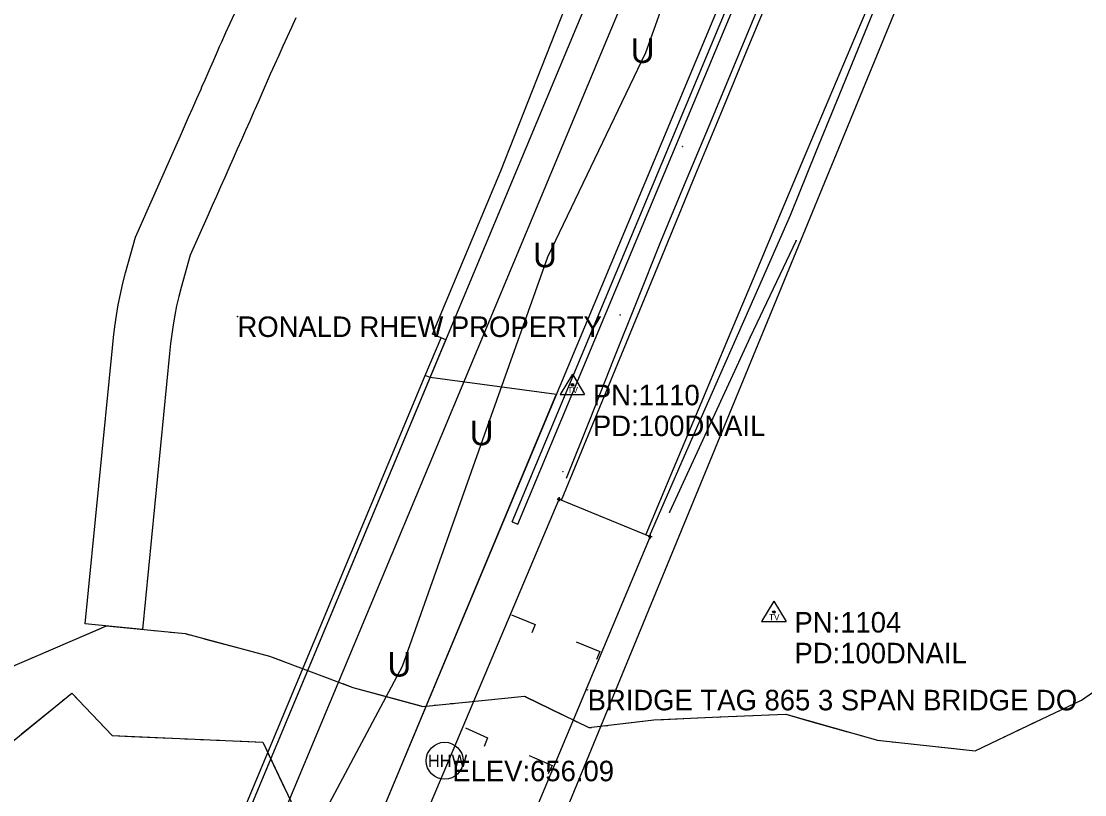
# Model space of a CAD drawing. Extents: x 1282810 to 1284464, y 402460 to 405899.
# Drawn here: x 1283291.6 to 1283550.7, y 403871.1 to 404059.6 of the extents above; entities that cross this region are included whole.
import ezdxf

# ---------------------------------------------------------------- set-up
doc = ezdxf.new("R2010")
doc.units = 0
for name, color, linetype in [('Default', 7, 'Continuous'), ('MOT_Bridge_Stage 2', 7, 'Continuous'), ('MOT_Proposed Road_Stage 2', 7, 'Continuous'), ('MOT_Shld_Stage 2', 7, 'Continuous'), ('MOT_Stage 1_Conc Ditch Paving', 7, 'Continuous'), ('MOT_Stage 2_Retaining Wall', 7, 'Continuous'), ('S_BASELINE', 7, 'Continuous'), ('S_BRIDGE', 7, 'Continuous'), ('S_EDGE_CONCRETE', 7, 'Continuous'), ('S_EDGE_PAVEMENT', 7, 'Continuous'), ('S_GUARDRAIL', 7, 'Continuous'), ('S_HIST_HIGH_WATER', 7, 'Continuous'), ('S_HIST_HIGH_WATER_ANNOT', 7, 'Continuous'), ('S_MSC_PT_SYM', 7, 'Continuous'), ('S_RDW_PT_SYM', 7, 'Continuous'), ('S_SECONDARY_CTL', 7, 'Continuous'), ('S_SECONDARY_CTL_ANNOT', 7, 'Continuous'), ('S_SHOULDER', 7, 'Continuous'), ('S_STR_PT_SYM', 7, 'Continuous'), ('S_STREAM', 7, 'Continuous'), ('S_SURVEY_TEXT_ANNOT', 7, 'Continuous'), ('S_UNDERGROUND_CABLE', 7, 'Continuous')]:
    doc.layers.add(name, color=color, linetype=linetype)

msp = doc.modelspace()

# ---------------------------------------------------------------- linework, layer by layer
at = {"layer": 'MOT_Bridge_Stage 2'}
for p, q in [((1283390.08, 403973.25), (1283393.94, 403982.47)), ((1283395.09, 403981.99), (1283393.94, 403982.47)), ((1283391.24, 403972.77), (1283395.09, 403981.99)), ((1283326.31, 403820.53), (1283390.08, 403973.25)), ((1283327.46, 403820.05), (1283391.24, 403972.77)), ((1283391.24, 403972.77), (1283390.08, 403973.25)), ((1283391.24, 403972.77), (1283390.08, 403973.25)), ((1283422.02, 403968.62), (1283391.24, 403972.77)), ((1283358.34, 403816.13), (1283421.92, 403968.39))]:
    msp.add_line(p, q, dxfattribs=at)
at = {"layer": 'MOT_Proposed Road_Stage 2'}
for p, q in [((1283334.68, 403816.57), (1283508.7, 404233.27)), ((1283354.98, 403808.09), (1283529, 404224.79))]:
    msp.add_line(p, q, dxfattribs=at)
at = {"layer": 'MOT_Shld_Stage 2'}
for p, q in [((1283327.3, 403819.65), (1283501.32, 404236.35)), ((1283327.3, 403819.65), (1283501.32, 404236.35)), ((1283327.3, 403819.65), (1283501.32, 404236.35)), ((1283327.3, 403819.65), (1283501.32, 404236.35)), ((1283327.3, 403819.65), (1283501.32, 404236.35)), ((1283327.3, 403819.65), (1283501.32, 404236.35)), ((1283408.48, 404023.13), (1283472.69, 404185.96)), ((1283391.86, 403983.34), (1283408.48, 404023.13)), ((1283393.94, 403982.47), (1283391.86, 403983.34))]:
    msp.add_line(p, q, dxfattribs=at)
at = {"layer": 'MOT_Stage 1_Conc Ditch Paving'}
msp.add_line((1283321.17, 403911.4), (1283307.24, 403912.77), dxfattribs=at)
for points in [[(1283319.47, 404007.02), (1283329.39, 404029.36), (1283330.4, 404031.65), (1283331.41, 404033.93), (1283332.42, 404036.22), (1283333.43, 404038.5), (1283334.43, 404040.79), (1283335.44, 404043.08), (1283335.67, 404043.6), (1283336.44, 404045.37), (1283337.44, 404047.65), (1283338.44, 404049.94), (1283339.44, 404052.23), (1283339.98, 404053.47), (1283340.48, 404054.56), (1283341.51, 404056.84), (1283342.55, 404059.11), (1283343.58, 404061.39)], [(1283358.5, 404060.42), (1283357.46, 404058.11), (1283356.42, 404055.83), (1283355.39, 404053.55), (1283354.36, 404051.27), (1283353.32, 404049), (1283352.84, 404047.94), (1283352.32, 404046.75), (1283351.32, 404044.46), (1283350.32, 404042.17), (1283349.32, 404039.88), (1283348.54, 404038.11), (1283348.31, 404037.58), (1283347.31, 404035.29), (1283346.3, 404033), (1283345.29, 404030.71), (1283344.28, 404028.42), (1283343.27, 404026.13), (1283342.25, 404023.85), (1283341.24, 404021.56), (1283340.22, 404019.27), (1283339.2, 404016.99), (1283338.18, 404014.7), (1283337.16, 404012.42), (1283332.77, 404002.62)], [(1283307.24, 403912.77), (1283313.85, 403980.02), (1283314.11, 403982.58), (1283314.44, 403985.23), (1283314.83, 403987.88), (1283315.28, 403990.51), (1283315.81, 403993.14), (1283316.4, 403995.75), (1283317.05, 403998.34), (1283319.47, 404007.02)], [(1283332.77, 404002.62), (1283330.58, 403994.75), (1283330.01, 403992.5), (1283329.5, 403990.23), (1283329.05, 403987.95), (1283328.65, 403985.66), (1283328.31, 403983.36), (1283328.03, 403981.05), (1283327.79, 403978.64), (1283321.17, 403911.4)]]:
    msp.add_lwpolyline(points, dxfattribs=at)
at = {"layer": 'MOT_Stage 2_Retaining Wall'}
for p, q in [((1283411.24, 403937.63), (1283530.85, 404224.02)), ((1283412.63, 403937.05), (1283532.23, 404223.44)), ((1283411.24, 403937.63), (1283412.63, 403937.05))]:
    msp.add_line(p, q, dxfattribs=at)
at = {"layer": 'S_BASELINE'}
msp.add_line((1283396.79, 403800.11), (1283700.58, 404538.68), dxfattribs=at)
at = {"layer": 'S_BRIDGE'}
for p, q in [((1283386.52, 403857.44), (1283422.73, 403943.16)), ((1283422.73, 403943.16), (1283444.84, 403934.02)), ((1283444.84, 403934.02), (1283408.77, 403848.06))]:
    msp.add_line(p, q, dxfattribs=at)
at = {"layer": 'S_EDGE_CONCRETE'}
for points in [[(1283411.07, 403914.97), (1283416.87, 403912.6), (1283416.03, 403910.58)], [(1283426.84, 403908.35), (1283432.62, 403906.02), (1283431.79, 403904.09)], [(1283399.84, 403887.41), (1283405.22, 403884.99), (1283404.41, 403882.88)], [(1283415.38, 403880.64), (1283420.95, 403878.2), (1283420.05, 403876.23)]]:
    msp.add_lwpolyline(points, dxfattribs=at)
at = {"layer": 'S_EDGE_PAVEMENT'}
for points in [[(1283501.97, 404072.63), (1283495.51, 404057.64), (1283489.28, 404042.83), (1283483.05, 404028.02), (1283476.82, 404013.2), (1283470.59, 403998.39), (1283463.89, 403982.42), (1283457.19, 403966.45), (1283450.49, 403950.48), (1283443.8, 403934.51)], [(1283475.3, 404069.12), (1283468.85, 404053.54), (1283462.4, 404037.96), (1283455.95, 404022.37), (1283447.76, 404002.49), (1283439.57, 403982.61), (1283431.38, 403962.73), (1283423.18, 403942.85)]]:
    msp.add_lwpolyline(points, dxfattribs=at)
at = {"layer": 'S_GUARDRAIL'}
for p, q in [((1283480.45, 404006.2), (1283469.2, 403982.66)), ((1283469.2, 403982.66), (1283449.54, 403939.94))]:
    msp.add_line(p, q, dxfattribs=at)
at = {"layer": 'S_HIST_HIGH_WATER'}
msp.add_circle((1283394.8, 403879.4), 4.5, dxfattribs=at)
at = {"layer": 'S_MSC_PT_SYM'}
for points in [[(1283344.32, 403987.67), (1283344.32, 403987.72), (1283344.32, 403987.67), (1283344.27, 403987.67), (1283344.32, 403987.67), (1283344.32, 403987.62), (1283344.32, 403987.67), (1283344.37, 403987.67)], [(1283429.63, 403896.68), (1283429.63, 403896.73), (1283429.63, 403896.68), (1283429.58, 403896.68), (1283429.63, 403896.68), (1283429.63, 403896.63), (1283429.63, 403896.68), (1283429.68, 403896.68)]]:
    msp.add_lwpolyline(points, dxfattribs=at)
at = {"layer": 'S_RDW_PT_SYM'}
for points in [[(1283452.72, 404029.12), (1283452.72, 404029.17), (1283452.72, 404029.12), (1283452.67, 404029.12), (1283452.72, 404029.12), (1283452.72, 404029.07), (1283452.72, 404029.12), (1283452.77, 404029.12)], [(1283480.45, 404006.2), (1283480.45, 404006.25), (1283480.45, 404006.2), (1283480.4, 404006.2), (1283480.45, 404006.2), (1283480.45, 404006.15), (1283480.45, 404006.2), (1283480.5, 404006.2)], [(1283437.56, 403988.04), (1283437.56, 403988.09), (1283437.56, 403988.04), (1283437.51, 403988.04), (1283437.56, 403988.04), (1283437.56, 403987.99), (1283437.56, 403988.04), (1283437.61, 403988.04)], [(1283469.2, 403982.66), (1283469.2, 403982.71), (1283469.2, 403982.66), (1283469.15, 403982.66), (1283469.2, 403982.66), (1283469.2, 403982.61), (1283469.2, 403982.66), (1283469.25, 403982.66)], [(1283423.6, 403949.86), (1283423.6, 403949.91), (1283423.6, 403949.86), (1283423.55, 403949.86), (1283423.6, 403949.86), (1283423.6, 403949.81), (1283423.6, 403949.86), (1283423.65, 403949.86)], [(1283449.54, 403939.94), (1283449.54, 403939.99), (1283449.54, 403939.94), (1283449.49, 403939.94), (1283449.54, 403939.94), (1283449.54, 403939.89), (1283449.54, 403939.94), (1283449.59, 403939.94)]]:
    msp.add_lwpolyline(points, dxfattribs=at)
at = {"layer": 'S_SECONDARY_CTL'}
for p, q in [((1283425.92, 403973.63), (1283422.91, 403968.67)), ((1283425.92, 403973.63), (1283428.87, 403968.67)), ((1283422.91, 403968.67), (1283428.87, 403968.67)), ((1283475.02, 403918.25), (1283472.01, 403913.3)), ((1283475.02, 403918.25), (1283477.97, 403913.3)), ((1283472.01, 403913.3), (1283477.97, 403913.3))]:
    msp.add_line(p, q, dxfattribs=at)
for centre, radius in [((1283425.92, 403971.02), 0.311), ((1283425.92, 403971.02), 0.183), ((1283425.92, 403971.02), 0.103), ((1283475.02, 403915.64), 0.311), ((1283475.02, 403915.64), 0.183), ((1283475.02, 403915.64), 0.103)]:
    msp.add_circle(centre, radius, dxfattribs=at)
at = {"layer": 'S_SHOULDER'}
for points in [[(1283444.67, 403934.14), (1283453.25, 403953.69), (1283461.84, 403973.25), (1283470.43, 403992.81), (1283479.02, 404012.36), (1283485.34, 404027.85), (1283491.67, 404043.34), (1283497.99, 404058.83), (1283504.32, 404074.32), (1283510.99, 404088.84), (1283517.66, 404103.36), (1283524.33, 404117.88), (1283530.99, 404132.4), (1283537.64, 404146.88), (1283544.28, 404161.36), (1283550.92, 404175.84), (1283557.57, 404190.32), (1283563.12, 404202.23), (1283568.68, 404214.14), (1283574.24, 404226.06), (1283579.8, 404237.97), (1283579.85, 404238.09)], [(1283424.49, 403948.25), (1283430.23, 403962.66), (1283435.97, 403977.08), (1283441.72, 403991.49), (1283447.46, 404005.9), (1283453.25, 404019.79), (1283459.04, 404033.69), (1283464.83, 404047.59), (1283470.62, 404061.49), (1283476.77, 404076.07), (1283482.91, 404090.66), (1283489.05, 404105.25), (1283495.2, 404119.83), (1283500.76, 404133.93), (1283506.32, 404148.02), (1283514.46, 404173.11)]]:
    msp.add_lwpolyline(points, dxfattribs=at)
at = {"layer": 'S_STR_PT_SYM'}
for points in [[(1283422.73, 403943.16), (1283422.73, 403943.66), (1283422.73, 403943.16), (1283422.23, 403943.16), (1283422.73, 403943.16), (1283422.73, 403942.66), (1283422.73, 403943.16), (1283423.23, 403943.16)], [(1283444.84, 403934.02), (1283444.84, 403934.52), (1283444.84, 403934.02), (1283444.34, 403934.02), (1283444.84, 403934.02), (1283444.84, 403933.52), (1283444.84, 403934.02), (1283445.34, 403934.02)]]:
    msp.add_lwpolyline(points, dxfattribs=at)
at = {"layer": 'S_STREAM'}
for points in [[(1283277.03, 403897.09), (1283294.74, 403904.68), (1283312.44, 403912.26), (1283331.55, 403910.38), (1283352.1, 403904.92), (1283372.45, 403897.28), (1283389.44, 403892.64), (1283414.28, 403895.1), (1283429.96, 403887.46), (1283445.73, 403889.38), (1283461.81, 403890.06), (1283477.9, 403890.73), (1283500.23, 403884.39), (1283524.02, 403881.83), (1283536.98, 403887.99), (1283549.94, 403894.16), (1283563.09, 403903.37)], [(1283301.87, 403907.73), (1283310.94, 403911.62)], [(1283310.95, 403911.62), (1283312.44, 403912.26), (1283320.66, 403911.45)], [(1283323.97, 403911.13), (1283324.69, 403911.06)], [(1283327.9, 403910.74), (1283328.62, 403910.67)], [(1283331.83, 403910.31), (1283332.52, 403910.12)], [(1283336.22, 403909.14), (1283345.76, 403906.6)], [(1283294.06, 403904.39), (1283294.72, 403904.67)], [(1283297.69, 403905.94), (1283298.35, 403906.22)], [(1283345.77, 403906.6), (1283352.1, 403904.92), (1283355.21, 403903.75)], [(1283365.73, 403899.8), (1283366.4, 403899.55)], [(1283369.99, 403898.2), (1283372.45, 403897.28), (1283379.44, 403895.37)], [(1283155.14, 403780.67), (1283168.76, 403789.1), (1283182.38, 403797.52), (1283197.41, 403805.48), (1283208.78, 403811.07), (1283220.16, 403816.66), (1283233.26, 403832.25), (1283245.23, 403846.1), (1283257.2, 403859.95), (1283270.89, 403870.02), (1283284.59, 403880.1), (1283303.96, 403895.89), (1283313.81, 403885.53), (1283332.16, 403884.74), (1283350.5, 403883.96), (1283361.12, 403861.52), (1283371.83, 403855.95), (1283372.66, 403855.71)], [(1283301.7, 403894.05), (1283302.24, 403894.49)], [(1283304.62, 403895.19), (1283305.1, 403894.69)], [(1283379.44, 403895.37), (1283388.97, 403892.77)], [(1283404.66, 403894.15), (1283414.28, 403895.1), (1283414.46, 403895.02)], [(1283414.47, 403895.01), (1283423.35, 403890.69)], [(1283541.9, 403890.34), (1283549.94, 403894.16), (1283550.74, 403894.72)], [(1283291.65, 403885.85), (1283299.16, 403891.98)], [(1283307.29, 403892.38), (1283307.78, 403891.87)], [(1283392.27, 403892.92), (1283392.98, 403892.99)], [(1283396.2, 403893.31), (1283396.92, 403893.38)], [(1283400.13, 403893.7), (1283400.85, 403893.77)], [(1283310.37, 403889.15), (1283313.81, 403885.53), (1283318.5, 403885.33)], [(1283426.34, 403889.22), (1283426.99, 403888.91)], [(1283438.32, 403888.48), (1283445.73, 403889.38), (1283448.14, 403889.49)], [(1283448.15, 403889.49), (1283458.01, 403889.9)], [(1283461.34, 403890.04), (1283461.81, 403890.06), (1283462.06, 403890.07)], [(1283465.29, 403890.2), (1283466, 403890.23)], [(1283469.24, 403890.37), (1283469.95, 403890.4)], [(1283473.78, 403890.56), (1283477.9, 403890.73), (1283483.43, 403889.16)], [(1283483.44, 403889.16), (1283492.94, 403886.47)], [(1283429.89, 403887.49), (1283429.96, 403887.46), (1283430.6, 403887.54)], [(1283433.81, 403887.93), (1283434.52, 403888.02)], [(1283534.23, 403886.69), (1283534.88, 403886.99)], [(1283537.8, 403888.38), (1283538.45, 403888.69)], [(1283318.51, 403885.33), (1283328.2, 403884.91)], [(1283331.47, 403884.77), (1283332.16, 403884.74), (1283332.17, 403884.74)], [(1283335.34, 403884.6), (1283336.05, 403884.57)], [(1283339.22, 403884.44), (1283339.92, 403884.41)], [(1283343.68, 403884.25), (1283350.5, 403883.96), (1283351.73, 403881.37)], [(1283496.14, 403885.55), (1283496.83, 403885.36)], [(1283499.94, 403884.48), (1283500.23, 403884.39), (1283500.64, 403884.35)], [(1283503.86, 403884), (1283504.57, 403883.93)], [(1283530.67, 403884.99), (1283531.31, 403885.3)], [(1283351.73, 403881.36), (1283355.88, 403872.59)], [(1283508.38, 403883.51), (1283518.2, 403882.46)], [(1283518.21, 403882.45), (1283524.02, 403881.83), (1283527.66, 403883.56)]]:
    msp.add_lwpolyline(points, dxfattribs=at)
at = {"layer": 'S_UNDERGROUND_CABLE'}
for p, q in [((1283443.77, 404052), (1283475.95, 404140.97)), ((1283419.97, 404002.19), (1283443.77, 404052)), ((1283404.53, 403958.84), (1283419.97, 404002.19)), ((1283384.5, 403902.46), (1283404.53, 403958.84)), ((1283357.72, 403852.14), (1283384.5, 403902.46))]:
    msp.add_line(p, q, dxfattribs=at)

# ---------------------------------------------------------------- texts
at = {"layer": 'Default'}
for p in [(1283440.14, 404049.45), (1283416.34, 403999.65), (1283400.9, 403956.29), (1283380.87, 403899.91)]:
    msp.add_text('U', height=6, rotation=360, dxfattribs=at).set_placement(p)
at = {"layer": 'S_HIST_HIGH_WATER'}
msp.add_text('HHW', height=3, rotation=360, dxfattribs=at).set_placement((1283390.71, 403877.9))
at = {"layer": 'S_HIST_HIGH_WATER_ANNOT'}
msp.add_text(' ELEV:656.09', height=5, dxfattribs=at).set_placement((1283394.8, 403874.4))
at = {"layer": 'S_SECONDARY_CTL'}
for p in [(1283424.72, 403969.01), (1283473.82, 403913.63)]:
    msp.add_text('TV', height=1.5, rotation=360, dxfattribs=at).set_placement(p)
at = {"layer": 'S_SECONDARY_CTL_ANNOT'}
for s, p in [('PN:1110', (1283430.92, 403966.02)), ('PD:100DNAIL', (1283430.92, 403958.52)), ('PN:1104', (1283480.02, 403910.64)), ('PD:100DNAIL', (1283480.02, 403903.14))]:
    msp.add_text(s, height=5, dxfattribs=at).set_placement(p)
at = {"layer": 'S_SURVEY_TEXT_ANNOT'}
for s, p in [('RONALD RHEW PROPERTY', (1283344.32, 403982.67)), ('BRIDGE TAG 865 3 SPAN BRIDGE DO', (1283429.63, 403891.68))]:
    msp.add_text(s, height=5, dxfattribs=at).set_placement(p)

doc.saveas('drawing.dxf')
